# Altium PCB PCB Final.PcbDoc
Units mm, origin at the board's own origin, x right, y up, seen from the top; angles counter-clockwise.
Board outline 152.4 x 101.6 mm, 2 copper layers (Top Layer, Bottom Layer); 2 components, 0 nets, 88 pads, 4 vias.
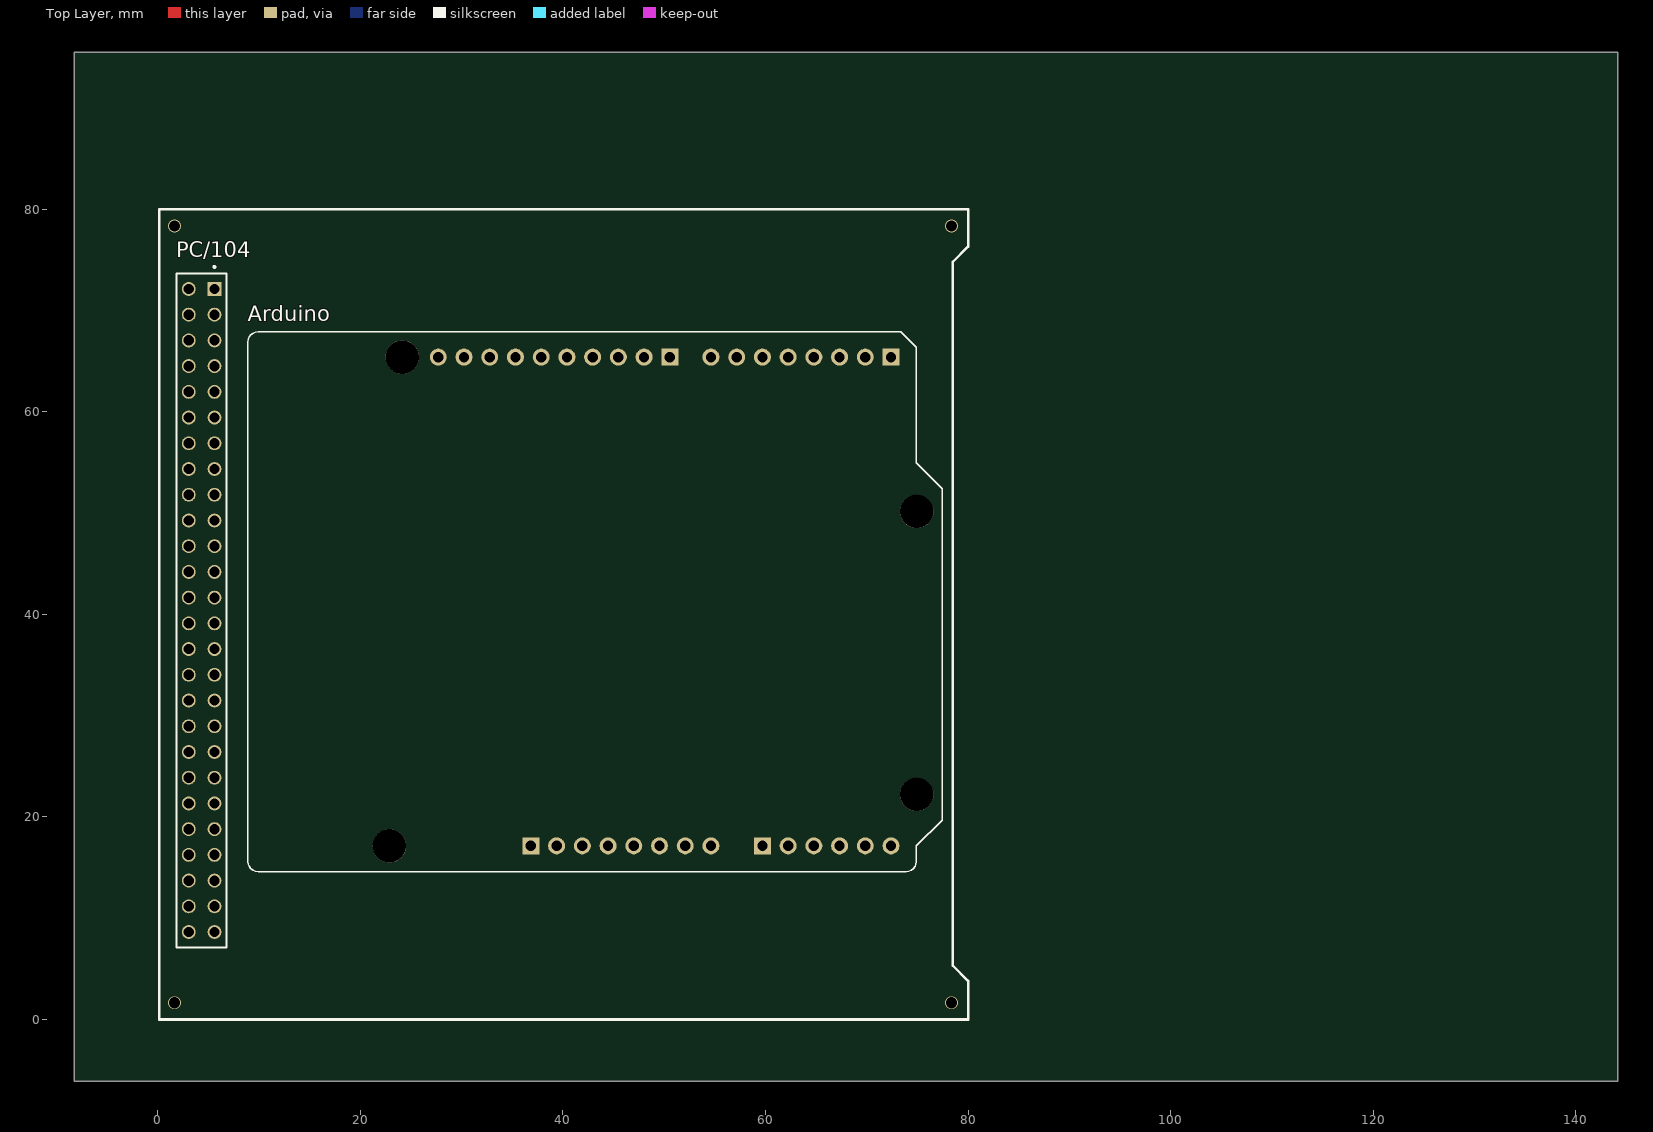
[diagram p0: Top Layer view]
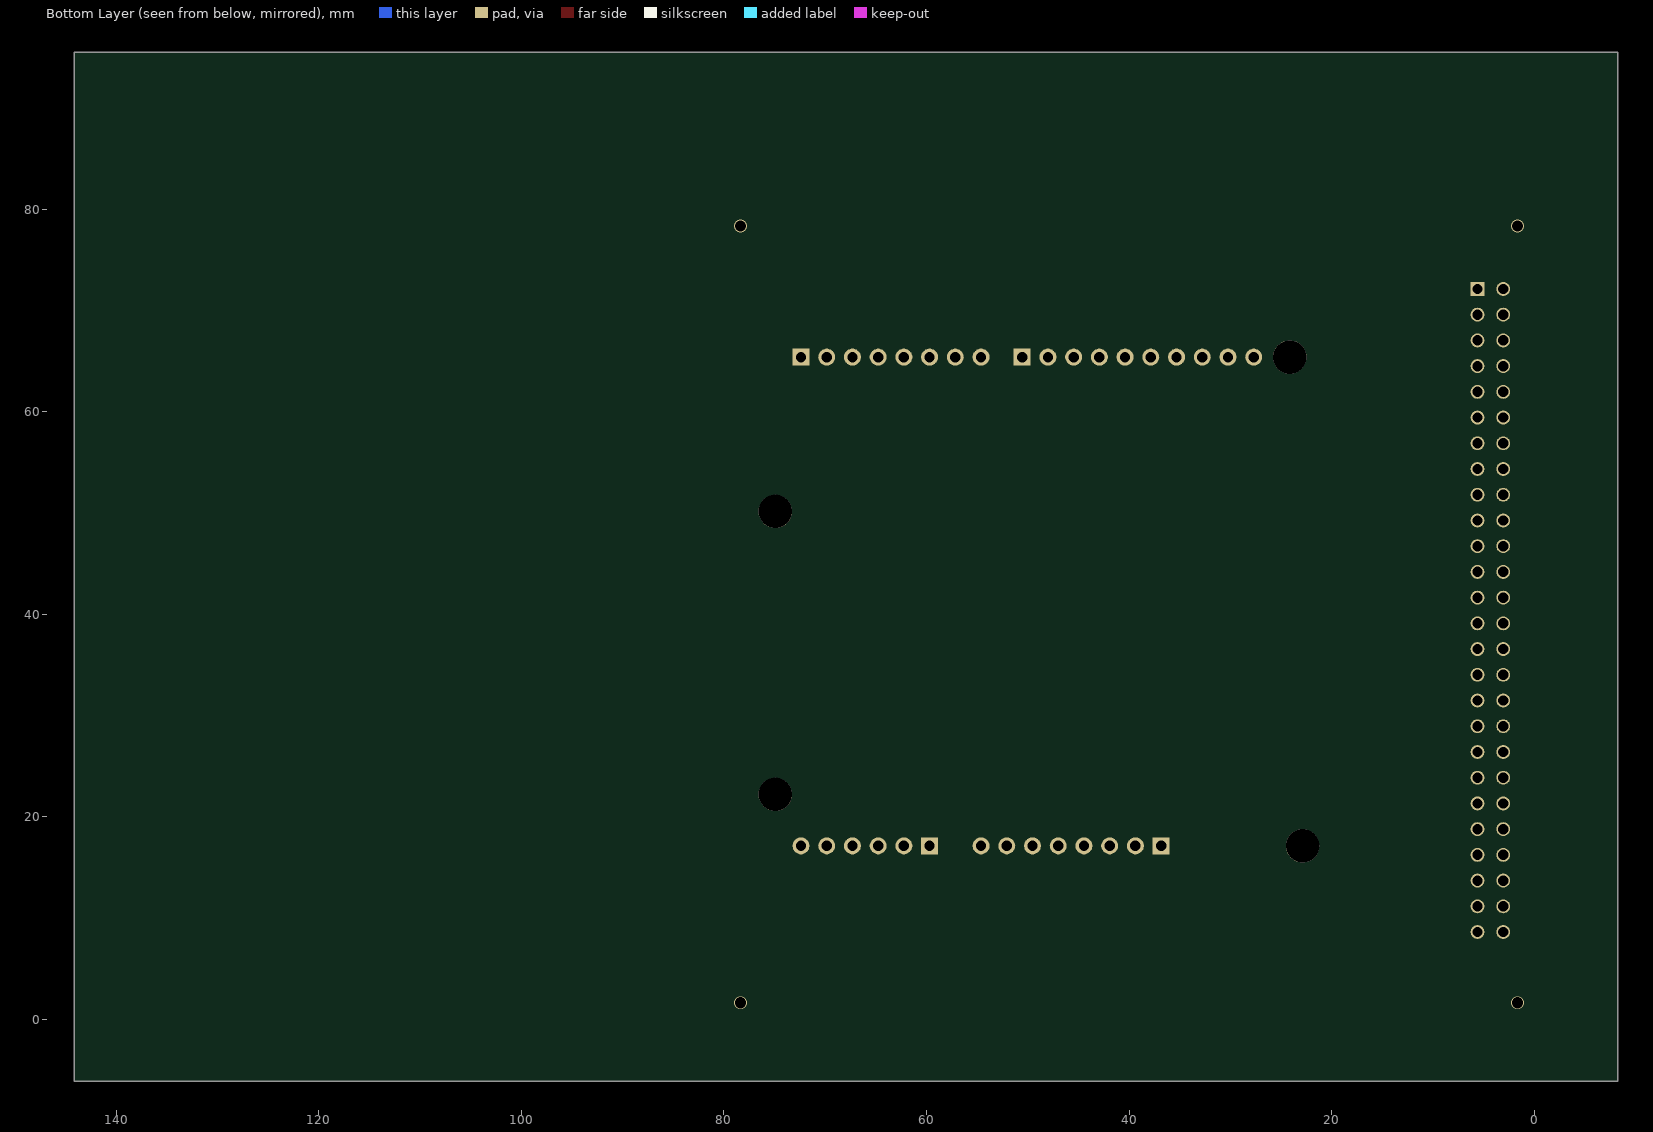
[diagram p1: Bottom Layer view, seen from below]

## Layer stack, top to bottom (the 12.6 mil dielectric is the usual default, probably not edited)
Top Solder: solder mask 0.0102, Solder Resist, Dk 3.5
Top Layer: signal copper 0.0356
Dielectric 1: dielectric 0.32, FR-4, Dk 4.8
Bottom Layer: signal copper 0.0356
Bottom Solder: solder mask 0.0102, Solder Resist, Dk 3.5

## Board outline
-8.255,-6.096 144.145,-6.096 144.145,95.504 -8.255,95.504

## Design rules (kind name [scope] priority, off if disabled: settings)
Clearance [All] p1: gap=0.254 ignorepadtopadclearanceinfootprint=FALSE except(0: Arc-Hole Track-Hole SMDPad-Hole THPad-Hole Via-Hole Fill-Hole Poly-Hole Region-Hole Text-Hole)
PolygonConnect [All] p1: connectstyle=Relief reliefconductorwidth=0.254 reliefentries=4 polygonreliefangle="90 Angle" airgapwidth=0.254
RoutingVias [All] p1: holewidth=0.711 width=1.27 viastyle="Through Hole" minholewidth=0.711 minwidth=1.27 maxholewidth=0.711 maxwidth=1.27
SolderMaskExpansion [All] p1: expansion=0.102
Width [All] p1: maxlimit=0.254 minlimit=0.254 preferedwidth=0.254
30 further rules are at their usual default settings.

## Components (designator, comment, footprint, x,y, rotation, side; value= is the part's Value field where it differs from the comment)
Arduino "Comment" ARDUINO_UNO_R3 8.89,14.605 r0 top
PC/104 "Comment" SAMTEC_ESQ-126-39-G-D 5.588,72.136 r90 top

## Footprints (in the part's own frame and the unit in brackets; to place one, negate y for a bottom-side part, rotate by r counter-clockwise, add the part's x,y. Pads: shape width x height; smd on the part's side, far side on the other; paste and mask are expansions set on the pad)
ARDUINO_UNO_R3 [mil]
  round 66 hole 40: 3V3(1400,100) 5V(1500,100) A1(2100,100) A2(2200,100) A3(2300,100) A4(2400,100) A4(SDA)(840,2000) A5(2500,100) A5(SCL)(740,2000) AREF(940,2000) D1(2400,2000) D2(2300,2000) D3(2200,2000) D4(2100,2000) D5(2000,2000) D6(1900,2000) D7(1800,2000) D9(1540,2000) D10(1440,2000) D11(1340,2000) D12(1240,2000) D13(1140,2000) GND_1(1700,100) GND_2(1600,100) GND_3(1040,2000) IOREF(1200,100) RST(1300,100) VIN(1800,100)
  rect 66x66 hole 40: A0(2000,100) D0(2500,2000) D8(1640,2000) P1(1100,100)
  round 129.92 hole 129.92 unplated: ""(550,100) ""(600,2000) ""(2600,300) ""(2600,1400)
  silkscreen extent 0,0 2698,2098
SAMTEC_ESQ-126-39-G-D [mm]
  rect 1.37x1.37 hole 1.02: 01(0,0)
  round 1.37 hole 1.02: 02(0,2.54) 03(-2.54,0) 04(-2.54,2.54) 05(-5.08,0) 06(-5.08,2.54) 07(-7.62,0) 08(-7.62,2.54) 09(-10.16,0) 10(-10.16,2.54) 11(-12.7,0) 12(-12.7,2.54) 13(-15.24,0) 14(-15.24,2.54) 15(-17.78,0) 16(-17.78,2.54) 17(-20.32,0) 18(-20.32,2.54) 19(-22.86,0) 20(-22.86,2.54) 21(-25.4,0) 22(-25.4,2.54) 23(-27.94,0) 24(-27.94,2.54) 25(-30.48,0) 26(-30.48,2.54) 27(-33.02,0) 28(-33.02,2.54) 29(-35.56,0) 30(-35.56,2.54) 31(-38.1,0) 32(-38.1,2.54) 33(-40.64,0) 34(-40.64,2.54) 35(-43.18,0) 36(-43.18,2.54) 37(-45.72,0) 38(-45.72,2.54) 39(-48.26,0) 40(-48.26,2.54) 41(-50.8,0) 42(-50.8,2.54) 43(-53.34,0) 44(-53.34,2.54) 45(-55.88,0) 46(-55.88,2.54) 47(-58.42,0) 48(-58.42,2.54) 49(-60.96,0) 50(-60.96,2.54) 51(-63.5,0) 52(-63.5,2.54)
  silkscreen extent -65.03,-1.2 2.27,3.74

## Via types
v1: diameter 1.27, hole 1.1, Top Layer to Bottom Layer, 4 vias

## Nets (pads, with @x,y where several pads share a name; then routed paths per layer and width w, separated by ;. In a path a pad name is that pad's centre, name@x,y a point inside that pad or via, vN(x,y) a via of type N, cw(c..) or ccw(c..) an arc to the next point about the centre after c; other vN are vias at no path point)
pads on no net: Arduino. Arduino.3V3 Arduino.5V Arduino.A0 Arduino.A1 Arduino.A2 Arduino.A3 Arduino.A4 Arduino.A4(SDA) Arduino.A5 Arduino.A5(SCL) Arduino.AREF Arduino.D0 Arduino.D1 Arduino.D2 Arduino.D3 Arduino.D4 Arduino.D5 Arduino.D6 Arduino.D7 Arduino.D8 Arduino.D9 Arduino.D10 Arduino.D11 Arduino.D12 Arduino.D13 Arduino.GND_1 Arduino.GND_2 Arduino.GND_3 Arduino.IOREF Arduino.P1 Arduino.RST Arduino.VIN PC/104.01 PC/104.02 PC/104.03 PC/104.04 PC/104.05 PC/104.06 PC/104.07 PC/104.08 PC/104.09 PC/104.10 PC/104.11 PC/104.12 PC/104.13 PC/104.14 PC/104.15 PC/104.16 PC/104.17 PC/104.18 PC/104.19 PC/104.20 PC/104.21 PC/104.22 PC/104.23 PC/104.24 PC/104.25 PC/104.26 PC/104.27 PC/104.28 PC/104.29 PC/104.30 PC/104.31 PC/104.32 PC/104.33 PC/104.34 PC/104.35 PC/104.36 PC/104.37 PC/104.38 PC/104.39 PC/104.40 PC/104.41 PC/104.42 PC/104.43 PC/104.44 PC/104.45 PC/104.46 PC/104.47 PC/104.48 PC/104.49 PC/104.50 PC/104.51 PC/104.52
copper on no net:
  other v1: 1.65,1.65 78.35,1.65 1.65,78.35 78.35,78.35

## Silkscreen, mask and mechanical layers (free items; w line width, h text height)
Top Overlay:
  lines w0.254: 0.127,0 1.905,0 80.01,0 80.01,3.81 78.486,5.334 78.486,23.527 78.486,59.15 78.486,74.803 80.01,76.327 80.01,80.01 0.127,80.01 0.127,0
